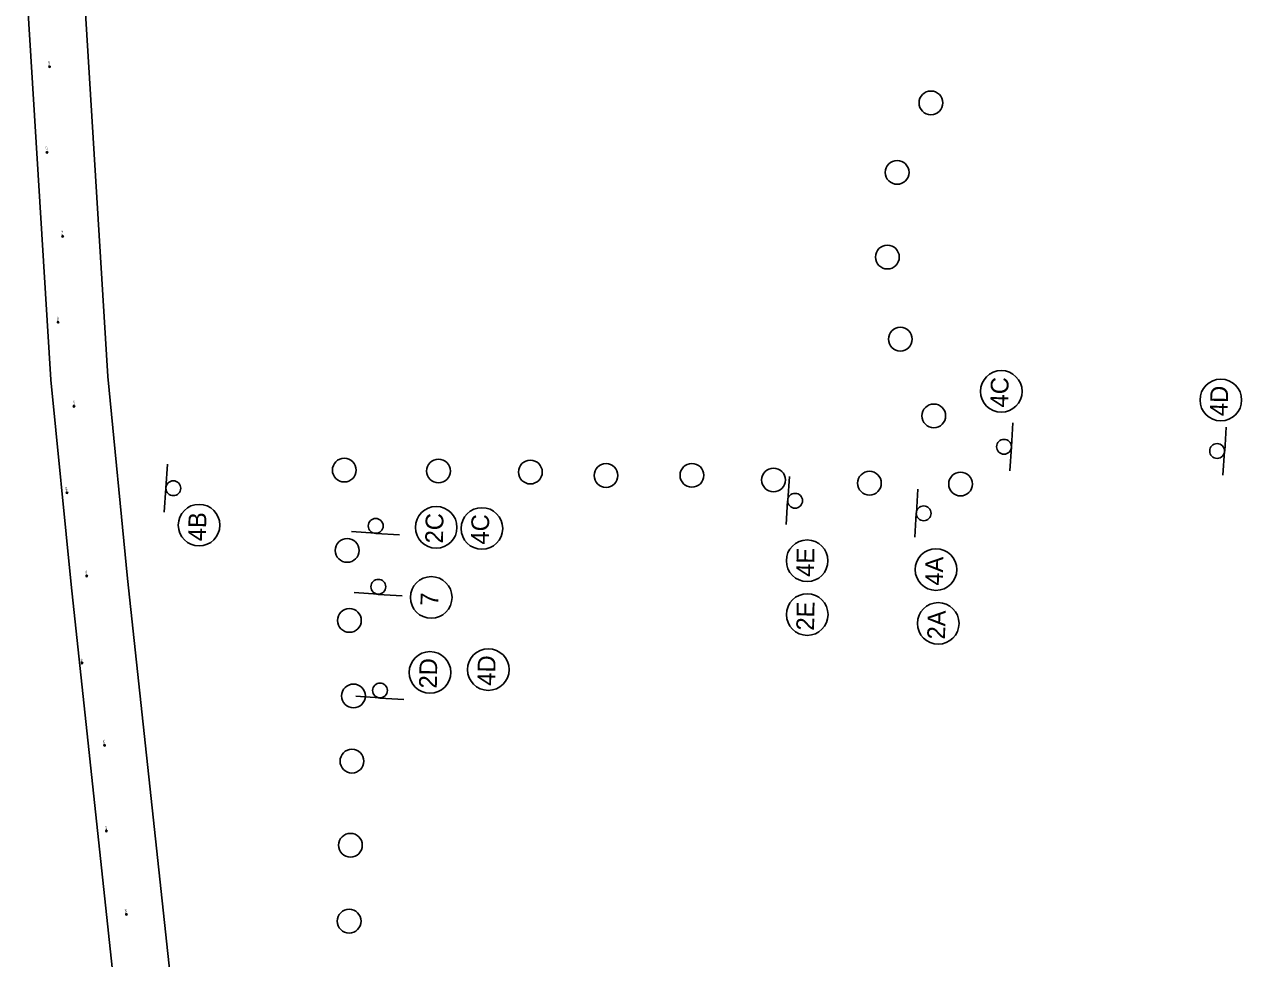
# Model space of a CAD drawing. Extents: x 327762 to 372792, y 127949 to 259367.
# Drawn here: x 355284 to 363857, y 182113 to 188696 of the extents above; entities that cross this region are included whole.
import ezdxf

# ---------------------------------------------------------------- set-up
doc = ezdxf.new("R2010")
doc.units = 0
for name, color, linetype in [('CA-TEXT', 7, 'Continuous'), ('CE-TOPO-CONC-SLAB', 7, 'Continuous'), ('E_SOIL_BORE1 [KAPUR_CADDS_LEVELS]', 7, 'Continuous'), ('E_SOIL_BORE2 [KAPUR_CADDS_LEVELS]', 7, 'Continuous'), ('P_MARK', 7, 'Continuous'), ('P_TC', 7, 'Continuous'), ('SIGNS-POLES', 7, 'Continuous')]:
    doc.layers.add(name, color=color, linetype=linetype)

msp = doc.modelspace()

# ---------------------------------------------------------------- linework, layer by layer
at = {"layer": 'CA-TEXT'}
for centre in [(362164.3, 186110.4), (363710.7, 186049.5), (356514.2, 185167.9), (358184.2, 185152.3), (358506.3, 185144.4), (360797, 184917), (361704.5, 184855.1), (358149.4, 184658.7), (360797.6, 184537.9), (361720.1, 184475.6), (358140.6, 184130.1), (358551.2, 184150.1)]:
    msp.add_circle(centre, 146.6, dxfattribs=at)
at = {"layer": 'CE-TOPO-CONC-SLAB'}
for centre in [(361668.9, 188142.9), (361430.8, 187653.4), (361362.1, 187056.8), (361453.3, 186478.2), (361688.7, 185937.6), (357537.1, 185555.9), (358200.5, 185549.3), (358847.6, 185542), (359380.4, 185517.8), (359985.5, 185519), (360560.2, 185486.2), (361235.5, 185463.5), (361877.6, 185457.6), (357557.2, 184990), (357572.9, 184496.5), (357601.7, 183964.4), (357591.1, 183505.2), (357580.3, 182912.4), (357571, 182377.7)]:
    msp.add_circle(centre, 83.7, dxfattribs=at)
at = {"layer": 'P_MARK'}
for p, q in [((355456.5, 188397.5), (355466.5, 188397.5)), ((355461.5, 188402.5), (355461.5, 188392.5)), ((355437.9, 187794.5), (355447.9, 187794.5)), ((355442.9, 187799.5), (355442.9, 187789.5)), ((355548.2, 187202.1), (355558.2, 187202.1)), ((355553.2, 187207.1), (355553.2, 187197.1)), ((355516.5, 186597.6), (355526.5, 186597.6)), ((355521.5, 186602.6), (355521.5, 186592.6)), ((355628.3, 186004.9), (355638.3, 186004.9)), ((355633.3, 186009.9), (355633.3, 185999.9)), ((355578.7, 185396.1), (355588.7, 185396.1)), ((355583.7, 185401.1), (355583.7, 185391.1)), ((355717.7, 184809.3), (355727.7, 184809.3)), ((355722.7, 184814.3), (355722.7, 184804.3)), ((355685.7, 184196.6), (355695.7, 184196.6)), ((355690.7, 184201.6), (355690.7, 184191.6)), ((355843.4, 183616.8), (355853.4, 183616.8)), ((355848.4, 183621.8), (355848.4, 183611.8)), ((355857, 183012.4), (355867, 183012.4)), ((355862, 183017.4), (355862, 183007.4)), ((355997.3, 182425.8), (356007.3, 182425.8)), ((356002.3, 182430.8), (356002.3, 182420.8))]:
    msp.add_line(p, q, dxfattribs=at)
for centre in [(355461.5, 188397.5), (355442.9, 187794.5), (355553.2, 187202.1), (355521.5, 186597.6), (355633.3, 186004.9), (355583.7, 185396.1), (355722.7, 184809.3), (355690.7, 184196.6), (355848.4, 183616.8), (355862, 183012.4), (356002.3, 182425.8)]:
    msp.add_circle(centre, 5, dxfattribs=at)
for centre, radius, start, end in [((355461.5, 188397.5), 4.5, 89.98693, 179.98693), ((355461.5, 188397.5), 4, 89.98693, 179.98693), ((355461.5, 188397.5), 3.5, 89.98693, 179.98693), ((355461.5, 188397.5), 3, 89.98693, 179.98693), ((355461.5, 188397.5), 2.5, 89.98693, 179.98693), ((355461.5, 188397.5), 2, 89.98693, 179.98693), ((355461.5, 188397.5), 1.5, 89.98693, 179.98693), ((355461.5, 188397.5), 1, 89.98693, 179.98693), ((355461.5, 188397.5), 0.5, 89.98693, 179.98693), ((355461.5, 188397.5), 4.5, 269.98693, 359.98693), ((355461.5, 188397.5), 4, 269.98693, 359.98693), ((355461.5, 188397.5), 3.5, 269.98693, 359.98693), ((355461.5, 188397.5), 3, 269.98693, 359.98693), ((355461.5, 188397.5), 2.5, 269.98693, 359.98693), ((355461.5, 188397.5), 2, 269.98693, 359.98693), ((355461.5, 188397.5), 1.5, 269.98693, 359.98693), ((355461.5, 188397.5), 1, 269.98693, 359.98693), ((355461.5, 188397.5), 0.5, 269.98693, 359.98693), ((355442.9, 187794.5), 4.5, 89.98693, 179.98693), ((355442.9, 187794.5), 4, 89.98693, 179.98693), ((355442.9, 187794.5), 3.5, 89.98693, 179.98693), ((355442.9, 187794.5), 3, 89.98693, 179.98693), ((355442.9, 187794.5), 2.5, 89.98693, 179.98693), ((355442.9, 187794.5), 2, 89.98693, 179.98693), ((355442.9, 187794.5), 1.5, 89.98693, 179.98693), ((355442.9, 187794.5), 1, 89.98693, 179.98693), ((355442.9, 187794.5), 0.5, 89.98693, 179.98693), ((355442.9, 187794.5), 4.5, 269.98693, 359.98693), ((355442.9, 187794.5), 4, 269.98693, 359.98693), ((355442.9, 187794.5), 3.5, 269.98693, 359.98693), ((355442.9, 187794.5), 3, 269.98693, 359.98693), ((355442.9, 187794.5), 2.5, 269.98693, 359.98693), ((355442.9, 187794.5), 2, 269.98693, 359.98693), ((355442.9, 187794.5), 1.5, 269.98693, 359.98693), ((355442.9, 187794.5), 1, 269.98693, 359.98693), ((355442.9, 187794.5), 0.5, 269.98693, 359.98693), ((355553.2, 187202.1), 4.5, 89.98693, 179.98693), ((355553.2, 187202.1), 4, 89.98693, 179.98693), ((355553.2, 187202.1), 3.5, 89.98693, 179.98693), ((355553.2, 187202.1), 3, 89.98693, 179.98693), ((355553.2, 187202.1), 2.5, 89.98693, 179.98693), ((355553.2, 187202.1), 2, 89.98693, 179.98693), ((355553.2, 187202.1), 1.5, 89.98693, 179.98693), ((355553.2, 187202.1), 1, 89.98693, 179.98693), ((355553.2, 187202.1), 0.5, 89.98693, 179.98693), ((355553.2, 187202.1), 4.5, 269.98693, 359.98693), ((355553.2, 187202.1), 4, 269.98693, 359.98693), ((355553.2, 187202.1), 3.5, 269.98693, 359.98693), ((355553.2, 187202.1), 3, 269.98693, 359.98693), ((355553.2, 187202.1), 2.5, 269.98693, 359.98693), ((355553.2, 187202.1), 2, 269.98693, 359.98693), ((355553.2, 187202.1), 1.5, 269.98693, 359.98693), ((355553.2, 187202.1), 1, 269.98693, 359.98693), ((355553.2, 187202.1), 0.5, 269.98693, 359.98693), ((355521.5, 186597.6), 4.5, 89.98693, 179.98693), ((355521.5, 186597.6), 4, 89.98693, 179.98693), ((355521.5, 186597.6), 3.5, 89.98693, 179.98693), ((355521.5, 186597.6), 3, 89.98693, 179.98693), ((355521.5, 186597.6), 2.5, 89.98693, 179.98693), ((355521.5, 186597.6), 2, 89.98693, 179.98693), ((355521.5, 186597.6), 1.5, 89.98693, 179.98693), ((355521.5, 186597.6), 1, 89.98693, 179.98693), ((355521.5, 186597.6), 0.5, 89.98693, 179.98693), ((355521.5, 186597.6), 4.5, 269.98693, 359.98693), ((355521.5, 186597.6), 4, 269.98693, 359.98693), ((355521.5, 186597.6), 3.5, 269.98693, 359.98693), ((355521.5, 186597.6), 3, 269.98693, 359.98693), ((355521.5, 186597.6), 2.5, 269.98693, 359.98693), ((355521.5, 186597.6), 2, 269.98693, 359.98693), ((355521.5, 186597.6), 1.5, 269.98693, 359.98693), ((355521.5, 186597.6), 1, 269.98693, 359.98693), ((355521.5, 186597.6), 0.5, 269.98693, 359.98693), ((355633.3, 186004.9), 4.5, 89.98693, 179.98693), ((355633.3, 186004.9), 4, 89.98693, 179.98693), ((355633.3, 186004.9), 3.5, 89.98693, 179.98693), ((355633.3, 186004.9), 3, 89.98693, 179.98693), ((355633.3, 186004.9), 2.5, 89.98693, 179.98693), ((355633.3, 186004.9), 2, 89.98693, 179.98693), ((355633.3, 186004.9), 1.5, 89.98693, 179.98693), ((355633.3, 186004.9), 1, 89.98693, 179.98693), ((355633.3, 186004.9), 0.5, 89.98693, 179.98693), ((355633.3, 186004.9), 4.5, 269.98693, 359.98693), ((355633.3, 186004.9), 4, 269.98693, 359.98693), ((355633.3, 186004.9), 3.5, 269.98693, 359.98693), ((355633.3, 186004.9), 3, 269.98693, 359.98693), ((355633.3, 186004.9), 2.5, 269.98693, 359.98693), ((355633.3, 186004.9), 2, 269.98693, 359.98693), ((355633.3, 186004.9), 1.5, 269.98693, 359.98693), ((355633.3, 186004.9), 1, 269.98693, 359.98693), ((355633.3, 186004.9), 0.5, 269.98693, 359.98693), ((355583.7, 185396.1), 4.5, 89.98693, 179.98693), ((355583.7, 185396.1), 4, 89.98693, 179.98693), ((355583.7, 185396.1), 3.5, 89.98693, 179.98693), ((355583.7, 185396.1), 3, 89.98693, 179.98693), ((355583.7, 185396.1), 2.5, 89.98693, 179.98693), ((355583.7, 185396.1), 2, 89.98693, 179.98693), ((355583.7, 185396.1), 1.5, 89.98693, 179.98693), ((355583.7, 185396.1), 1, 89.98693, 179.98693), ((355583.7, 185396.1), 0.5, 89.98693, 179.98693), ((355583.7, 185396.1), 4.5, 269.98693, 359.98693), ((355583.7, 185396.1), 4, 269.98693, 359.98693), ((355583.7, 185396.1), 3.5, 269.98693, 359.98693), ((355583.7, 185396.1), 3, 269.98693, 359.98693), ((355583.7, 185396.1), 2.5, 269.98693, 359.98693), ((355583.7, 185396.1), 2, 269.98693, 359.98693), ((355583.7, 185396.1), 1.5, 269.98693, 359.98693), ((355583.7, 185396.1), 1, 269.98693, 359.98693), ((355583.7, 185396.1), 0.5, 269.98693, 359.98693), ((355722.7, 184809.3), 4.5, 89.98693, 179.98693), ((355722.7, 184809.3), 4, 89.98693, 179.98693), ((355722.7, 184809.3), 3.5, 89.98693, 179.98693), ((355722.7, 184809.3), 3, 89.98693, 179.98693), ((355722.7, 184809.3), 2.5, 89.98693, 179.98693), ((355722.7, 184809.3), 2, 89.98693, 179.98693), ((355722.7, 184809.3), 1.5, 89.98693, 179.98693), ((355722.7, 184809.3), 1, 89.98693, 179.98693), ((355722.7, 184809.3), 0.5, 89.98693, 179.98693), ((355722.7, 184809.3), 4.5, 269.98693, 359.98693), ((355722.7, 184809.3), 4, 269.98693, 359.98693), ((355722.7, 184809.3), 3.5, 269.98693, 359.98693), ((355722.7, 184809.3), 3, 269.98693, 359.98693), ((355722.7, 184809.3), 2.5, 269.98693, 359.98693), ((355722.7, 184809.3), 2, 269.98693, 359.98693), ((355722.7, 184809.3), 1.5, 269.98693, 359.98693), ((355722.7, 184809.3), 1, 269.98693, 359.98693), ((355722.7, 184809.3), 0.5, 269.98693, 359.98693), ((355690.7, 184196.6), 4.5, 89.98693, 179.98693), ((355690.7, 184196.6), 4, 89.98693, 179.98693), ((355690.7, 184196.6), 3.5, 89.98693, 179.98693), ((355690.7, 184196.6), 3, 89.98693, 179.98693), ((355690.7, 184196.6), 2.5, 89.98693, 179.98693), ((355690.7, 184196.6), 2, 89.98693, 179.98693), ((355690.7, 184196.6), 1.5, 89.98693, 179.98693), ((355690.7, 184196.6), 1, 89.98693, 179.98693), ((355690.7, 184196.6), 0.5, 89.98693, 179.98693), ((355690.7, 184196.6), 4.5, 269.98693, 359.98693), ((355690.7, 184196.6), 4, 269.98693, 359.98693), ((355690.7, 184196.6), 3.5, 269.98693, 359.98693), ((355690.7, 184196.6), 3, 269.98693, 359.98693), ((355690.7, 184196.6), 2.5, 269.98693, 359.98693), ((355690.7, 184196.6), 2, 269.98693, 359.98693), ((355690.7, 184196.6), 1.5, 269.98693, 359.98693), ((355690.7, 184196.6), 1, 269.98693, 359.98693), ((355690.7, 184196.6), 0.5, 269.98693, 359.98693), ((355848.4, 183616.8), 4.5, 89.98693, 179.98693), ((355848.4, 183616.8), 4, 89.98693, 179.98693), ((355848.4, 183616.8), 3.5, 89.98693, 179.98693), ((355848.4, 183616.8), 3, 89.98693, 179.98693), ((355848.4, 183616.8), 2.5, 89.98693, 179.98693), ((355848.4, 183616.8), 2, 89.98693, 179.98693), ((355848.4, 183616.8), 1.5, 89.98693, 179.98693), ((355848.4, 183616.8), 1, 89.98693, 179.98693), ((355848.4, 183616.8), 0.5, 89.98693, 179.98693), ((355848.4, 183616.8), 4.5, 269.98693, 359.98693), ((355848.4, 183616.8), 4, 269.98693, 359.98693), ((355848.4, 183616.8), 3.5, 269.98693, 359.98693), ((355848.4, 183616.8), 3, 269.98693, 359.98693), ((355848.4, 183616.8), 2.5, 269.98693, 359.98693), ((355848.4, 183616.8), 2, 269.98693, 359.98693), ((355848.4, 183616.8), 1.5, 269.98693, 359.98693), ((355848.4, 183616.8), 1, 269.98693, 359.98693), ((355848.4, 183616.8), 0.5, 269.98693, 359.98693), ((355862, 183012.4), 4.5, 89.98693, 179.98693), ((355862, 183012.4), 4, 89.98693, 179.98693), ((355862, 183012.4), 3.5, 89.98693, 179.98693), ((355862, 183012.4), 3, 89.98693, 179.98693), ((355862, 183012.4), 2.5, 89.98693, 179.98693), ((355862, 183012.4), 2, 89.98693, 179.98693), ((355862, 183012.4), 1.5, 89.98693, 179.98693), ((355862, 183012.4), 1, 89.98693, 179.98693), ((355862, 183012.4), 0.5, 89.98693, 179.98693), ((355862, 183012.4), 4.5, 269.98693, 359.98693), ((355862, 183012.4), 4, 269.98693, 359.98693), ((355862, 183012.4), 3.5, 269.98693, 359.98693), ((355862, 183012.4), 3, 269.98693, 359.98693), ((355862, 183012.4), 2.5, 269.98693, 359.98693), ((355862, 183012.4), 2, 269.98693, 359.98693), ((355862, 183012.4), 1.5, 269.98693, 359.98693), ((355862, 183012.4), 1, 269.98693, 359.98693), ((355862, 183012.4), 0.5, 269.98693, 359.98693), ((356002.3, 182425.8), 4.5, 89.98693, 179.98693), ((356002.3, 182425.8), 4, 89.98693, 179.98693), ((356002.3, 182425.8), 3.5, 89.98693, 179.98693), ((356002.3, 182425.8), 3, 89.98693, 179.98693), ((356002.3, 182425.8), 2.5, 89.98693, 179.98693), ((356002.3, 182425.8), 2, 89.98693, 179.98693), ((356002.3, 182425.8), 1.5, 89.98693, 179.98693), ((356002.3, 182425.8), 1, 89.98693, 179.98693), ((356002.3, 182425.8), 0.5, 89.98693, 179.98693), ((356002.3, 182425.8), 4.5, 269.98693, 359.98693), ((356002.3, 182425.8), 4, 269.98693, 359.98693), ((356002.3, 182425.8), 3.5, 269.98693, 359.98693), ((356002.3, 182425.8), 3, 269.98693, 359.98693), ((356002.3, 182425.8), 2.5, 269.98693, 359.98693), ((356002.3, 182425.8), 2, 269.98693, 359.98693), ((356002.3, 182425.8), 1.5, 269.98693, 359.98693), ((356002.3, 182425.8), 1, 269.98693, 359.98693), ((356002.3, 182425.8), 0.5, 269.98693, 359.98693)]:
    msp.add_arc(centre, radius, start, end, dxfattribs=at)
at = {"layer": 'P_TC'}
for p, q in [((355471.2, 186190.8), (355283.6, 189224)), ((355691.8, 189129.9), (355870.5, 186215.5)), ((355612.9, 184748.7), (355471.2, 186190.8)), ((355870.5, 186215.5), (356010.7, 184791.4))]:
    msp.add_line(p, q, dxfattribs=at)
for points in [[(356010.7, 184791.4), (356404.2, 181123.3), (356466.9, 180787.9), (356513.6, 180550.2), (356602.1, 180279.7), (356741, 179932.9), (356921, 179635), (357119.9, 179365.3), (357302.9, 179137.3), (357638, 178834.1), (357970.9, 178543), (358585.9, 178064.8), (358972.8, 177765.7), (359287.4, 177446.4), (359568.2, 177108.6), (359781.6, 176804.9), (359973.6, 176484.4), (360151.9, 176070.5), (360266.6, 175727.9), (360318.3, 175542.9)], [(359933.1, 175435.2), (359884.1, 175610.5), (359777.9, 175927.7), (359616.8, 176301.7), (359446, 176586.9), (359250.3, 176865.3), (358990.6, 177177.7), (358706.9, 177465.7), (358340.8, 177748.6), (357716.2, 178234.3), (357372.1, 178535.2), (357010.9, 178862.1), (356802.9, 179121.3), (356588.2, 179412.3), (356381.8, 179753.9), (356226, 180143), (356125.8, 180449.1), (356074, 180712.7), (356008.1, 181065.2), (355612.9, 184748.7)]]:
    msp.add_lwpolyline(points, dxfattribs=at)
at = {"layer": 'SIGNS-POLES'}
for p, q in [((362246.7, 185888.2), (362236.8, 185719.7)), ((363747.7, 185858), (363737.8, 185689.5)), ((362235.4, 185718.6), (362224.2, 185550.2)), ((363736.4, 185688.4), (363725.2, 185520)), ((356280.7, 185429.5), (356291.9, 185597.8)), ((360660.4, 185341.3), (360671.7, 185509.6)), ((356269.4, 185259.9), (356279.4, 185428.3)), ((361566.1, 185252.6), (361577.3, 185421)), ((360649.1, 185171.6), (360659.1, 185340.1)), ((361554.8, 185083), (361564.7, 185251.5)), ((357757, 185111), (357588.6, 185122.3)), ((357926.6, 185099.7), (357758.2, 185109.7)), ((357775.5, 184681.6), (357607.1, 184692.9)), ((357945.1, 184670.3), (357776.7, 184680.3)), ((357787, 183951.1), (357618.7, 183962.3)), ((357956.7, 183939.8), (357788.2, 183949.8))]:
    msp.add_line(p, q, dxfattribs=at)
for centre in [(362183.5, 185720.1), (363684.5, 185689.9), (356332.6, 185428), (360712.3, 185339.8), (361618, 185251.1), (357758.5, 185162.9), (357777, 184733.5), (357788.5, 184003)]:
    msp.add_circle(centre, 52.2, dxfattribs=at)

# ---------------------------------------------------------------- texts
at = {"layer": 'CA-TEXT'}
for s, height, p in [('4C', 124.99, (362212, 185996.1)), ('4D', 124.99, (363758.4, 185935.2)), ('4B', 124.99, (356561.8, 185053.6)), ('2C', 124.99, (358231.8, 185038)), ('4C', 124.99, (358554, 185030.1)), ('4E', 124.99, (360844.6, 184802.7)), ('4A', 124.99, (361752.2, 184740.7)), ('7', 125, (358198.2, 184599)), ('2E', 124.99, (360845.2, 184423.6)), ('2A', 124.99, (361767.8, 184361.3)), ('2D', 124.99, (358188.3, 184015.8)), ('4D', 124.99, (358598.9, 184035.8))]:
    msp.add_text(s, height=height, rotation=88.84682, dxfattribs=at).set_placement(p)
at = {"layer": 'E_SOIL_BORE1 [KAPUR_CADDS_LEVELS]'}
for s, rotation, p in [('B107', 93.58677, (355445.9, 187804.7)), ('B108', 93.58677, (355556.8, 187211.2)), ('B105', 93.58677, (355526, 186606.3)), ('B104', 98.95705, (355727, 184816.6)), ('B101', 98.95705, (355694.1, 184204.3)), ('B102', 98.95705, (355851, 183624.3))]:
    msp.add_text(s, height=10, rotation=rotation, dxfattribs=at).set_placement(p)
at = {"layer": 'E_SOIL_BORE2 [KAPUR_CADDS_LEVELS]'}
for s, rotation, p in [('B110', 98.95705, (355465.6, 188405.1)), ('B106', 93.58677, (355638.1, 186013.3)), ('B103', 98.95705, (355587.5, 185404.5)), ('B99', 98.95705, (355865.6, 183022.4)), ('B100', 98.95705, (356005.7, 182433.2))]:
    msp.add_text(s, height=10, rotation=rotation, dxfattribs=at).set_placement(p)

doc.saveas('drawing.dxf')
